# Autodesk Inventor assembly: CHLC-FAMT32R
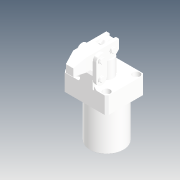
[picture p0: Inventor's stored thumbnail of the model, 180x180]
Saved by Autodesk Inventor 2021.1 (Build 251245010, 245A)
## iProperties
Created: 2019-04
Part Number: CHLC-FAMT32R
Description: STEP AP214
Document SubType Name: Assembly
Designer: user
Title: CHLC-FAMT32R.STEP
Revision Number: ÈÎºÎ
Sending System: SolidWorks 2016
Preprocessor: SwSTEP 2.0
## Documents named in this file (11)
- D:\Vault_2016\Projekty\Clamptek\Hydraulic\CHLC\CHLC-32\Inventor\CHLC-FAMT32R\CHLC-FAMT32R.iam
- D:\Vault_2016\Projekty\Clamptek\Hydraulic\CHLC\CHLC-32\Inventor\CHLC-FAMT32R\benti_1.ipt
- D:\Vault_2016\Projekty\Clamptek\Hydraulic\CHLC\CHLC-32\Inventor\CHLC-FAMT32R\CHLC-32-02_1.ipt
- D:\Vault_2016\Projekty\Clamptek\Hydraulic\CHLC\CHLC-32\Inventor\CHLC-FAMT32R\CHLC-32-03_1.ipt
- D:\Vault_2016\Projekty\Clamptek\Hydraulic\CHLC\CHLC-32\Inventor\CHLC-FAMT32R\CHLC-32-04_1_1.ipt
- D:\Vault_2016\Projekty\Clamptek\Hydraulic\CHLC\CHLC-32\Inventor\CHLC-FAMT32R\CHLC-32-08_1_1.ipt
- D:\Vault_2016\Projekty\Clamptek\Hydraulic\CHLC\CHLC-32\Inventor\CHLC-FAMT32R\chlc-famT32BT-HANJIE.ipt
- D:\Vault_2016\Projekty\Clamptek\Hydraulic\CHLC\CHLC-32\Inventor\CHLC-FAMT32R\CZL10µ÷ËÙ·§.ipt
- D:\Vault_2016\Projekty\Clamptek\Hydraulic\CHLC\CHLC-32\Inventor\CHLC-FAMT32R\socket set screw flat point_iso_ISO 4026 - M5 x 6-S.ipt
- D:\Vault_2016\Projekty\Clamptek\Hydraulic\CHLC\CHLC-32\Inventor\CHLC-FAMT32R\LHC01D-32-01_1.ipt
- D:\Vault_2016\Projekty\Clamptek\Hydraulic\CHLC\CHLC-32\Inventor\CHLC-FAMT32R\Ñ¹±Û.ipt
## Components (19 placed, 19 different names)
1. benti_1_1
2. CHLC-32-02_1_2
3. CHLC-32-03_1_3
4. CHLC-32-03_1_4
5. CHLC-32-04_1_1_5
6. CHLC-32-08_1_1_6
7. chlc-famT32BT-HANJIE_7
8. CZL10µ÷ËÙ·§_8
9. socket set screw flat point_iso_ISO 4026 - M5 x 6-S_9
10. LHC01D-32-01_1_10
11. LHC01D-32-01_1_11
12. LHC01D-32-01_1_12
13. LHC01D-32-01_1_13
14. LHC01D-32-01_1_14
15. LHC01D-32-01_1_15
16. CHLC-32-04_1_1_16
17. socket set screw flat point_iso_ISO 4026 - M5 x 6-S_17
18. socket set screw flat point_iso_ISO 4026 - M5 x 6-S_18
19. Ñ¹±Û_19
